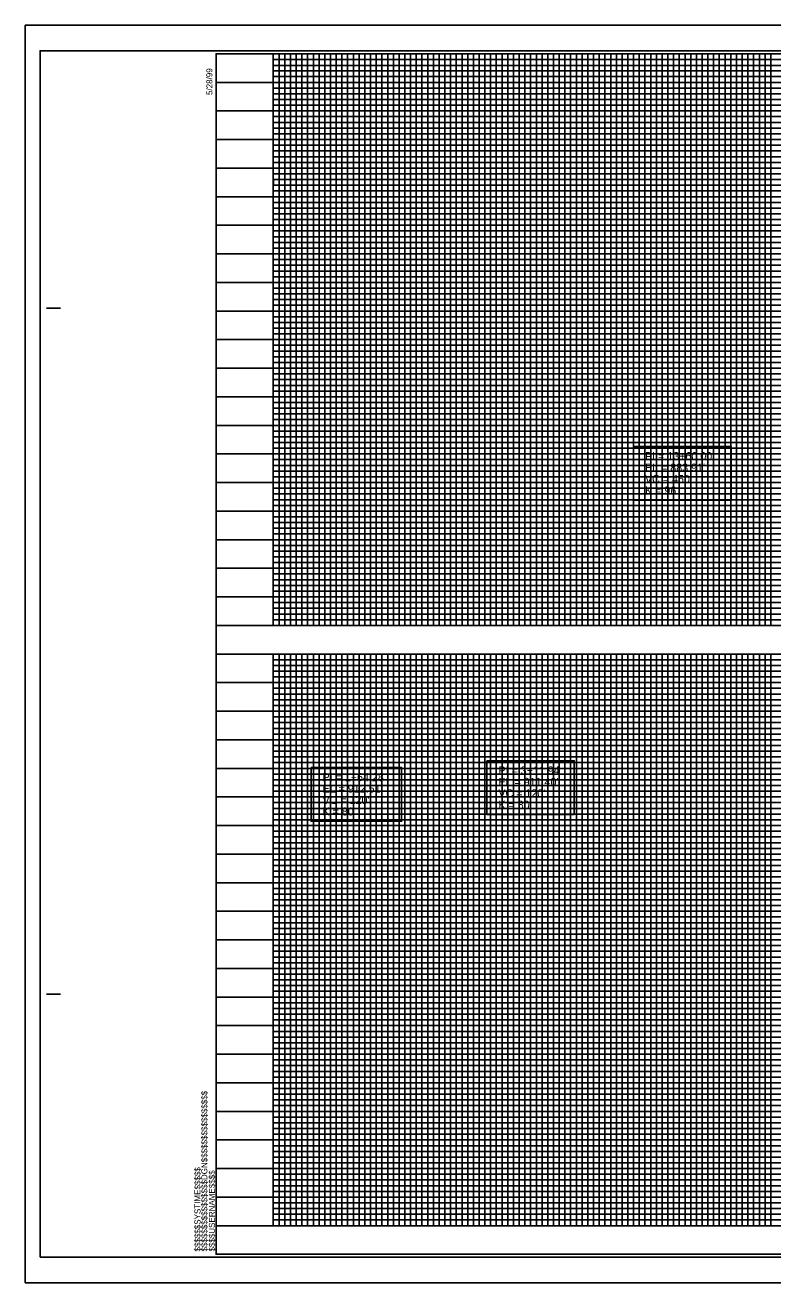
# Model space of a CAD drawing. Extents: x 1648862 to 1650889, y 802691 to 803791.
# Drawn here: x 1648862 to 1649516, y 802691 to 803791 of the extents above; entities that cross this region are included whole.
import ezdxf

# ---------------------------------------------------------------- set-up
doc = ezdxf.new("R2010")
doc.units = 0
for name, color, linetype in [('Prop Grid Mask', 7, 'Continuous'), ('Prop Vertical Profile Curve Label', 7, 'Continuous'), ('Prop VPI Label', 7, 'Continuous'), ('Sheet Cutting Line CELL', 7, 'Continuous'), ('Sheet DOT Grid CELL', 7, 'Continuous'), ('Sheet Layout Profile Border Port 1', 7, 'Continuous'), ('Sheet Layout Profile Border Port 2', 7, 'Continuous'), ('Sheet Plot Border Inside CELL', 7, 'Continuous'), ('Sheet Plot Border Outside CELL', 7, 'Continuous'), ('Sheet Profile CELL', 7, 'Continuous'), ('Sheet Profile Grid Major CELL', 7, 'Continuous'), ('Sheet Profile Grid Middle CELL', 7, 'Continuous'), ('Sheet Profile Grid Minor CELL', 7, 'Continuous')]:
    doc.layers.add(name, color=color, linetype=linetype)

msp = doc.modelspace()

# ---------------------------------------------------------------- linework, layer by layer
at = {"layer": 'Prop Grid Mask'}
for points in [[(1649394.3, 803422.6), (1649394.3, 803375.6), (1649479.6, 803375.6), (1649479.6, 803422.6)], [(1649266.1, 803147.7), (1649266.1, 803100.7), (1649342.4, 803100.7), (1649342.4, 803147.7)], [(1649112.3, 803141.8), (1649112.3, 803094.8), (1649191.4, 803094.8), (1649191.4, 803141.8)]]:
    msp.add_lwpolyline(points, close=True, dxfattribs=at)
at = {"layer": 'Sheet Cutting Line CELL'}
for p, q in [((1650546.3, 803791), (1648862.3, 803791)), ((1648862.3, 803791), (1648862.3, 802691)), ((1648862.3, 802691), (1650546.3, 802691))]:
    msp.add_line(p, q, dxfattribs=at)
at = {"layer": 'Sheet DOT Grid CELL'}
for p, q in [((1649079.3, 803266), (1649079.3, 803766)), ((1649129.3, 803266), (1649129.3, 803766)), ((1649179.3, 803266), (1649179.3, 803766)), ((1649229.3, 803266), (1649229.3, 803766)), ((1649279.3, 803266), (1649279.3, 803766)), ((1649329.3, 803266), (1649329.3, 803766)), ((1649379.3, 803266), (1649379.3, 803766)), ((1649429.3, 803266), (1649429.3, 803766)), ((1649479.3, 803266), (1649479.3, 803766)), ((1650329.2, 803716), (1649029.3, 803716)), ((1650329.2, 803666), (1649029.3, 803666)), ((1650329.3, 803616), (1649029.3, 803616)), ((1650529.3, 803566), (1649029.3, 803566)), ((1650529.3, 803516), (1649029.3, 803516)), ((1650529.3, 803466), (1649029.3, 803466)), ((1650529.3, 803416), (1649029.3, 803416)), ((1650529.3, 803366), (1649029.3, 803366)), ((1650529.3, 803316), (1649029.3, 803316)), ((1649029.3, 803241), (1650529.2, 803241)), ((1649079.3, 803241), (1649079.3, 802741)), ((1649129.3, 803241), (1649129.3, 802741)), ((1649179.3, 803241), (1649179.3, 802741)), ((1649229.3, 803241), (1649229.3, 802741)), ((1649279.3, 803241), (1649279.3, 802741)), ((1649329.3, 803241), (1649329.3, 802741)), ((1649379.3, 803241), (1649379.3, 802741)), ((1649429.3, 803241), (1649429.3, 802741)), ((1649479.3, 803241), (1649479.3, 802741)), ((1649029.3, 803191), (1650529.2, 803191)), ((1649029.3, 803141), (1650529.2, 803141)), ((1649029.3, 803091), (1650529.2, 803091)), ((1649029.3, 803041), (1650529.2, 803041)), ((1649029.3, 802991), (1650529.2, 802991)), ((1649029.3, 802941), (1650529.2, 802941)), ((1649029.3, 802891), (1650529.2, 802891)), ((1649029.3, 802841), (1650529.2, 802841)), ((1649029.3, 802791), (1650529.2, 802791))]:
    msp.add_line(p, q, dxfattribs=at)
at = {"layer": 'Sheet Layout Profile Border Port 1'}
msp.add_lwpolyline([(1649079.3, 803605), (1649079.3, 803266), (1650479.3, 803266), (1650479.3, 803605)], dxfattribs=at)
at = {"layer": 'Sheet Layout Profile Border Port 2'}
msp.add_lwpolyline([(1649079.3, 803241), (1650479.3, 803241), (1650479.3, 802741), (1649079.3, 802741)], close=True, dxfattribs=at)
at = {"layer": 'Sheet Plot Border Inside CELL'}
msp.add_lwpolyline([(1648875.3, 802713.5), (1650541.8, 802713.5), (1650541.8, 803768.6), (1648875.3, 803768.6)], close=True, dxfattribs=at)
at = {"layer": 'Sheet Plot Border Outside CELL'}
msp.add_lwpolyline([(1648862.3, 802691), (1650546.3, 802691), (1650546.3, 803791), (1648862.3, 803791)], close=True, dxfattribs=at)
at = {"layer": 'Sheet Profile CELL'}
for p, q in [((1648880.8, 803543.5), (1648893.3, 803543.5)), ((1649029.3, 803266), (1650529.3, 803266)), ((1649029.3, 803241), (1650529.3, 803241)), ((1648880.8, 802943.5), (1648893.3, 802943.5)), ((1650529.3, 802741), (1649029.3, 802741)), ((1649029.3, 802716), (1650529.3, 802716)), ((1649029.3, 802716), (1649029.3, 802716)), ((1649029.3, 802716), (1649029.3, 802716)), ((1649029.3, 802716), (1649029.3, 802716)), ((1649029.3, 802716), (1649029.3, 802716)), ((1649029.3, 802716), (1649029.3, 802716)), ((1649029.3, 802716), (1649029.3, 802716)), ((1649029.3, 802716), (1649029.3, 802716))]:
    msp.add_line(p, q, dxfattribs=at)
msp.add_lwpolyline([(1650529.3, 803766), (1649029.3, 803766), (1649029.3, 802716), (1650529.3, 802716)], close=True, dxfattribs=at)
msp.add_lwpolyline([(1649066.8, 802716), (1649066.8, 802716)], dxfattribs=at)
at = {"layer": 'Sheet Profile Grid Major CELL'}
msp.add_line((1649029.3, 802741), (1649029.3, 802741), dxfattribs=at)
for points in [[(1649079.3, 803766), (1649079.3, 803266), (1649129.3, 803266), (1649129.3, 803766), (1649179.3, 803766), (1649179.3, 803266), (1649229.3, 803266), (1649229.3, 803766), (1649279.3, 803766), (1649279.3, 803266), (1649329.3, 803266), (1649329.3, 803766), (1649379.3, 803766), (1649379.3, 803266), (1649429.3, 803266), (1649429.3, 803766), (1649479.3, 803766), (1649479.3, 803266), (1649529.3, 803266)], [(1649029.3, 803716), (1650329.3, 803716)], [(1650329.3, 803666), (1649029.3, 803666), (1649029.3, 803616), (1650329.3, 803616)], [(1650529.3, 803566), (1649029.3, 803566), (1649029.3, 803516), (1650529.3, 803516)], [(1650529.3, 803466), (1649029.3, 803466), (1649029.3, 803416), (1650529.3, 803416)], [(1650529.3, 803366), (1649029.3, 803366), (1649029.3, 803366), (1649029.3, 803316), (1650529.3, 803316)], [(1649079.3, 803241), (1649079.3, 802741), (1649129.3, 802741), (1649129.3, 803241), (1649179.3, 803241), (1649179.3, 802741), (1649229.3, 802741), (1649229.3, 803241), (1649279.3, 803241), (1649279.3, 802741), (1649329.3, 802741), (1649329.3, 803241), (1649379.3, 803241), (1649379.3, 802741), (1649429.3, 802741), (1649429.3, 803241), (1649479.3, 803241), (1649479.3, 802741), (1649529.3, 802741)], [(1650529.3, 803191), (1649029.3, 803191)], [(1650529.3, 803141), (1649029.3, 803141), (1649029.3, 803091), (1650529.3, 803091)], [(1650529.3, 803041), (1649029.3, 803041), (1649029.3, 802991), (1650529.3, 802991)], [(1650529.3, 802941), (1649029.3, 802941), (1649029.3, 802891), (1650529.3, 802891)], [(1650529.3, 802841), (1649029.3, 802841), (1649029.3, 802841), (1649029.3, 802791), (1650529.3, 802791)], [(1650529.3, 802741), (1649029.3, 802741)]]:
    msp.add_lwpolyline(points, dxfattribs=at)
at = {"layer": 'Sheet Profile Grid Middle CELL'}
msp.add_line((1649029.3, 803741), (1650179.3, 803741), dxfattribs=at)
for points in [[(1649104.3, 803766), (1649104.3, 803266), (1649154.3, 803266), (1649154.3, 803766), (1649204.3, 803766), (1649204.3, 803266), (1649254.3, 803266), (1649254.3, 803766), (1649304.3, 803766), (1649304.3, 803266), (1649354.3, 803266), (1649354.3, 803766), (1649404.3, 803766), (1649404.3, 803266), (1649454.3, 803266), (1649454.3, 803766), (1649504.3, 803766), (1649504.3, 803266), (1649554.3, 803266)], [(1650329.3, 803691), (1649029.3, 803691), (1649029.3, 803641), (1650329.3, 803641)], [(1650529.3, 803591), (1649029.3, 803591), (1649029.3, 803541), (1650354.3, 803541)], [(1650529.3, 803491), (1649029.3, 803491), (1649029.3, 803441), (1650529.3, 803441)], [(1650529.3, 803391), (1649029.3, 803391), (1649029.3, 803341), (1650529.3, 803341)], [(1650529.3, 803291), (1649029.3, 803291)], [(1649054.3, 803241), (1649104.3, 803241), (1649104.3, 802741), (1649154.3, 802741), (1649154.3, 803241), (1649204.3, 803241), (1649204.3, 802741), (1649254.3, 802741), (1649254.3, 803241), (1649304.3, 803241), (1649304.3, 802741), (1649354.3, 802741), (1649354.3, 803241), (1649404.3, 803241), (1649404.3, 802741), (1649454.3, 802741), (1649454.3, 803241), (1649504.3, 803241), (1649504.3, 802741), (1649554.3, 802741)], [(1649029.3, 803216), (1650529.3, 803216)], [(1650529.3, 803166), (1649029.3, 803166), (1649029.3, 803116), (1650529.3, 803116)], [(1650529.3, 803066), (1649029.3, 803066), (1649029.3, 803016), (1650529.3, 803016)], [(1650529.3, 802966), (1649029.3, 802966), (1649029.3, 802916), (1650529.3, 802916)], [(1650529.3, 802866), (1649029.3, 802866), (1649029.3, 802816), (1650529.3, 802816)], [(1650529.3, 802766), (1649029.3, 802766)]]:
    msp.add_lwpolyline(points, dxfattribs=at)
at = {"layer": 'Sheet Profile Grid Minor CELL'}
for p, q in [((1649079.3, 803761), (1650179.3, 803761)), ((1649079.3, 803756), (1649079.3, 803756)), ((1649079.3, 803756), (1649079.3, 803756)), ((1649079.3, 803756), (1649079.3, 803756)), ((1649079.3, 803756), (1649079.3, 803756)), ((1650179.3, 803756), (1649079.3, 803755.7)), ((1649079.3, 803751), (1650179.3, 803751)), ((1650329.2, 803631), (1649079.3, 803631)), ((1650329.3, 803626), (1649079.3, 803626)), ((1650329.3, 803621), (1649079.3, 803621)), ((1649079.3, 803611), (1650329.3, 803611)), ((1650329.3, 803606), (1649079.3, 803606)), ((1649079.3, 803601), (1650479.3, 803601)), ((1650479.3, 803581), (1649079.3, 803581)), ((1649079.3, 803576), (1650479.3, 803576)), ((1650479.3, 803556), (1649079.3, 803556)), ((1649079.3, 803551), (1650479.3, 803551)), ((1650479.3, 803531), (1649079.3, 803531)), ((1649079.3, 803526), (1650479.3, 803526)), ((1650479.3, 803521), (1649079.3, 803521)), ((1649079.3, 803511), (1650479.3, 803511)), ((1650479.3, 803506), (1649079.3, 803506)), ((1649079.3, 803501), (1650479.3, 803501)), ((1650479.3, 803496), (1649079.3, 803496)), ((1649079.3, 803486), (1650479.3, 803486)), ((1650479.3, 803481), (1649079.3, 803481)), ((1649079.3, 803476), (1650479.3, 803476)), ((1650479.3, 803471), (1649079.3, 803471)), ((1649079.3, 803461), (1650479.3, 803461)), ((1650479.3, 803456), (1649079.3, 803456)), ((1649079.3, 803451), (1650479.3, 803451)), ((1650479.3, 803446), (1649079.3, 803446)), ((1649079.3, 803436), (1650479.3, 803436)), ((1650479.3, 803431), (1649079.3, 803431)), ((1649079.3, 803426), (1650479.3, 803426)), ((1650479.3, 803421), (1649079.3, 803421)), ((1649079.3, 803411), (1650479.3, 803411)), ((1650479.3, 803406), (1649079.3, 803406)), ((1649079.3, 803401), (1650479.3, 803401)), ((1650479.3, 803396), (1649079.3, 803396)), ((1649079.3, 803386), (1650479.3, 803386)), ((1650479.3, 803381), (1649079.3, 803381)), ((1650479.3, 803376), (1649079.3, 803376)), ((1650479.3, 803371), (1649079.3, 803371)), ((1649079.3, 803361), (1650479.3, 803361)), ((1650479.3, 803356), (1649079.3, 803356)), ((1649079.3, 803351), (1650479.3, 803351)), ((1650479.3, 803346), (1649079.3, 803346)), ((1649079.3, 803336), (1650479.3, 803336)), ((1650479.3, 803331), (1649079.3, 803331)), ((1649079.3, 803326), (1650479.3, 803326)), ((1650479.3, 803321), (1649079.3, 803321)), ((1649079.3, 803311), (1650479.3, 803311)), ((1650479.3, 803306), (1649079.3, 803306)), ((1649079.3, 803301), (1650479.3, 803301)), ((1650479.3, 803296), (1649079.3, 803296)), ((1649079.3, 803286), (1650479.3, 803286)), ((1650479.3, 803281), (1649079.3, 803281)), ((1649079.3, 803276), (1650479.3, 803276)), ((1649079.3, 803236), (1650479.3, 803236)), ((1650479.3, 803231), (1649079.3, 803231)), ((1649079.3, 803226), (1650479.3, 803226)), ((1650479.3, 803221), (1649079.3, 803221)), ((1649079.3, 803211), (1650479.3, 803211)), ((1650479.3, 803206), (1649079.3, 803206)), ((1649079.3, 803201), (1650479.3, 803201)), ((1650479.3, 803196), (1649079.3, 803196)), ((1649079.3, 803186), (1650479.3, 803186)), ((1650479.3, 803181), (1649079.3, 803181)), ((1649079.3, 803176), (1650479.3, 803176)), ((1650479.3, 803171), (1649079.3, 803171)), ((1649079.3, 803161), (1650479.3, 803161)), ((1650479.3, 803156), (1649079.3, 803156)), ((1649079.3, 803151), (1650479.3, 803151)), ((1650479.3, 803146), (1649079.3, 803146)), ((1649079.3, 803136), (1650479.3, 803136)), ((1650479.3, 803131), (1649079.3, 803131)), ((1649079.3, 803126), (1650479.3, 803126)), ((1650479.3, 803121), (1649079.3, 803121)), ((1649079.3, 803111), (1650479.3, 803111)), ((1650479.3, 803106), (1649079.3, 803106)), ((1649079.3, 803101), (1650479.3, 803101)), ((1650479.3, 803096), (1649079.3, 803096)), ((1649079.3, 803086), (1650479.3, 803086)), ((1650479.3, 803081), (1649079.3, 803081)), ((1649079.3, 803076), (1650479.3, 803076)), ((1650479.3, 803071), (1649079.3, 803071)), ((1649079.3, 803061), (1650479.3, 803061)), ((1650479.3, 803056), (1649079.3, 803056)), ((1649079.3, 803051), (1650479.3, 803051)), ((1650479.3, 803046), (1649079.3, 803046.2)), ((1649079.3, 803036), (1650479.3, 803036)), ((1650479.3, 803031), (1649079.3, 803031)), ((1649079.3, 803026), (1650479.3, 803026)), ((1650479.3, 803021), (1649079.3, 803021)), ((1649079.3, 803011), (1650479.3, 803011)), ((1650479.3, 803006), (1649079.3, 803006)), ((1649079.3, 803001), (1650479.3, 803001)), ((1650479.3, 802996), (1649079.3, 802996)), ((1649079.3, 802986), (1650479.3, 802986)), ((1650479.3, 802981), (1649079.3, 802981)), ((1649079.3, 802976), (1650479.3, 802976)), ((1650479.3, 802971), (1649079.3, 802971)), ((1649079.3, 802961), (1650479.3, 802961)), ((1650479.3, 802956), (1649079.3, 802956)), ((1649079.3, 802951), (1650479.3, 802951)), ((1650479.3, 802946), (1649079.3, 802946)), ((1649079.3, 802936), (1650479.3, 802936)), ((1650479.3, 802931), (1649079.3, 802931)), ((1649079.3, 802926), (1650479.3, 802926)), ((1650479.3, 802921), (1649079.3, 802921)), ((1649079.3, 802911), (1650479.3, 802911)), ((1650479.3, 802906), (1649079.3, 802906)), ((1649079.3, 802901), (1650479.3, 802901)), ((1650479.3, 802896), (1649079.3, 802896)), ((1649079.3, 802886), (1650479.3, 802886)), ((1650479.3, 802881), (1649079.3, 802881)), ((1649079.3, 802876), (1650479.3, 802876)), ((1650479.3, 802871), (1649079.3, 802871)), ((1649079.3, 802861), (1650479.3, 802861)), ((1650479.3, 802856), (1649079.3, 802856)), ((1649079.3, 802851), (1650479.3, 802851)), ((1650479.3, 802846), (1649079.3, 802846)), ((1649079.3, 802836), (1650479.3, 802836)), ((1650479.3, 802831), (1649079.3, 802831)), ((1649079.3, 802826), (1650479.3, 802826)), ((1650479.3, 802821), (1649079.3, 802821)), ((1649079.3, 802811), (1650479.3, 802811)), ((1650479.3, 802806), (1649079.3, 802806)), ((1649079.3, 802801), (1650479.3, 802801)), ((1650479.3, 802796), (1649079.3, 802796)), ((1649079.3, 802786), (1650479.3, 802786)), ((1650479.3, 802781), (1649079.3, 802781)), ((1649079.3, 802776), (1650479.3, 802776)), ((1650479.3, 802771), (1649079.3, 802771)), ((1649079.3, 802761), (1650479.3, 802761)), ((1650479.3, 802756), (1649079.3, 802756)), ((1649079.3, 802751), (1650479.3, 802751)), ((1649079.3, 802746), (1650479.3, 802746))]:
    msp.add_line(p, q, dxfattribs=at)
for points in [[(1649084.3, 803766), (1649084.3, 803266), (1649089.3, 803266), (1649089.3, 803766), (1649094.3, 803766), (1649094.3, 803266), (1649099.3, 803266), (1649099.3, 803766), (1649109.3, 803766), (1649109.3, 803266), (1649114.3, 803266), (1649114.3, 803766), (1649119.3, 803766), (1649119.3, 803266), (1649124.3, 803266), (1649134.3, 803266), (1649139.3, 803266), (1649139.3, 803766), (1649144.3, 803766), (1649144.3, 803266), (1649149.3, 803266), (1649149.3, 803766), (1649159.3, 803766), (1649159.3, 803266), (1649164.3, 803266), (1649164.3, 803766), (1649169.3, 803766), (1649169.3, 803266), (1649174.3, 803266), (1649174.3, 803766), (1649184.3, 803766), (1649184.3, 803266), (1649189.3, 803266), (1649189.3, 803766), (1649194.3, 803766), (1649194.3, 803266), (1649199.3, 803266), (1649199.3, 803766), (1649209.3, 803766), (1649209.3, 803266), (1649214.3, 803266), (1649214.3, 803766), (1649219.3, 803766), (1649219.3, 803266), (1649224.3, 803266), (1649224.3, 803766), (1649234.3, 803766), (1649234.3, 803266), (1649239.3, 803266), (1649239.3, 803766), (1649244.3, 803766), (1649244.3, 803266), (1649249.3, 803266), (1649249.3, 803766), (1649259.3, 803766), (1649259.3, 803266), (1649264.3, 803266), (1649264.3, 803766), (1649269.3, 803766), (1649269.3, 803266), (1649274.3, 803266), (1649274.3, 803766), (1649284.3, 803766), (1649284.3, 803266), (1649289.3, 803266), (1649289.3, 803766), (1649294.3, 803766), (1649294.3, 803266)], [(1649124.3, 803266), (1649124.3, 803766), (1649134.3, 803766), (1649134.3, 803266)], [(1649294.3, 803266), (1649299.3, 803266), (1649299.3, 803766), (1649309.3, 803766), (1649309.3, 803266), (1649314.3, 803266), (1649314.3, 803766), (1649319.3, 803766), (1649319.3, 803266), (1649324.3, 803266), (1649324.3, 803766), (1649334.3, 803766), (1649334.3, 803266), (1649339.3, 803266), (1649339.3, 803766), (1649344.3, 803766), (1649344.3, 803266), (1649349.3, 803266), (1649349.3, 803766), (1649359.3, 803766), (1649359.3, 803266), (1649364.3, 803266), (1649364.3, 803766), (1649369.3, 803766), (1649369.3, 803266), (1649374.3, 803266), (1649374.3, 803766), (1649384.3, 803766), (1649384.3, 803266), (1649389.3, 803266), (1649389.3, 803766), (1649394.3, 803766), (1649394.3, 803266), (1649399.3, 803266), (1649399.3, 803766), (1649409.3, 803766), (1649409.3, 803266), (1649414.3, 803266), (1649414.3, 803766), (1649419.3, 803766), (1649419.3, 803266), (1649424.3, 803266), (1649424.3, 803766), (1649434.3, 803766), (1649434.3, 803266), (1649439.3, 803266), (1649439.3, 803766), (1649444.3, 803766), (1649444.3, 803266), (1649449.3, 803266), (1649449.3, 803766), (1649459.3, 803766), (1649459.3, 803266), (1649464.3, 803266), (1649464.3, 803766), (1649469.3, 803766), (1649469.3, 803266), (1649474.3, 803266), (1649474.3, 803766), (1649484.3, 803766), (1649484.3, 803266), (1649489.3, 803266), (1649489.3, 803766), (1649494.3, 803766), (1649494.3, 803266), (1649499.3, 803266), (1649499.3, 803766), (1649509.3, 803766), (1649509.3, 803266), (1649514.3, 803266), (1649514.3, 803766), (1649519.3, 803766)], [(1650179.3, 803746), (1649079.3, 803746), (1649079.3, 803736), (1650329.3, 803736)], [(1650329.2, 803731), (1649079.3, 803731), (1649079.3, 803726), (1650329.3, 803726)], [(1650329.3, 803721), (1649079.3, 803721), (1649079.3, 803711), (1650329.3, 803711)], [(1650329.3, 803706), (1649079.3, 803706), (1649079.3, 803701), (1650329.3, 803701)], [(1650329.3, 803696), (1649079.3, 803696), (1649079.3, 803686), (1650329.3, 803686)], [(1650329.3, 803681), (1649079.3, 803681), (1649079.3, 803676), (1650329.3, 803676)], [(1650329.3, 803671), (1649079.3, 803671), (1649079.3, 803661), (1650329.3, 803661)], [(1650329.3, 803655.9), (1649079.4, 803655.9), (1649079.4, 803651), (1650329.3, 803651)], [(1650329.3, 803646), (1649079.3, 803646), (1649079.3, 803636), (1650329.3, 803636)], [(1650479.3, 803596), (1649079.3, 803596), (1649079.3, 803586), (1650479.3, 803586)], [(1650479.3, 803571), (1649079.3, 803571), (1649079.3, 803561), (1650479.3, 803561)], [(1650479.3, 803546), (1649079.3, 803546), (1649079.3, 803536), (1650479.3, 803536)], [(1650479.3, 803271), (1649079.3, 803271)], [(1650479.3, 803271), (1649079.3, 803271)], [(1649079.3, 803241), (1649084.3, 803241), (1649084.3, 802741), (1649089.3, 802741), (1649089.3, 803241), (1649094.3, 803241), (1649094.3, 802741), (1649099.3, 802741), (1649099.3, 803241), (1649109.3, 803241), (1649109.3, 802741), (1649114.3, 802741), (1649114.3, 803241), (1649119.3, 803241), (1649119.3, 802741), (1649124.3, 802741), (1649134.3, 802741), (1649139.3, 802741), (1649139.3, 803241), (1649144.3, 803241), (1649144.3, 802741), (1649149.3, 802741), (1649149.3, 803241), (1649159.3, 803241), (1649159.3, 802741), (1649164.3, 802741), (1649164.3, 803241), (1649169.3, 803241), (1649169.3, 802741), (1649174.3, 802741), (1649174.3, 803241), (1649184.3, 803241), (1649184.3, 802741), (1649189.3, 802741), (1649189.3, 803241), (1649194.3, 803241), (1649194.3, 802741), (1649199.3, 802741), (1649199.3, 803241), (1649209.3, 803241), (1649209.3, 802741), (1649214.3, 802741), (1649214.3, 803241), (1649219.3, 803241), (1649219.3, 802741), (1649224.3, 802741), (1649224.3, 803241), (1649234.3, 803241), (1649234.3, 802741), (1649239.3, 802741), (1649239.3, 803241), (1649244.3, 803241), (1649244.3, 802741), (1649249.3, 802741), (1649249.3, 803241), (1649259.3, 803241), (1649259.3, 802741), (1649264.3, 802741), (1649264.3, 803241), (1649269.3, 803241), (1649269.3, 802741), (1649274.3, 802741), (1649274.3, 803241), (1649284.3, 803241), (1649284.3, 802741), (1649289.3, 802741), (1649289.3, 803241), (1649294.3, 803241), (1649294.3, 802741)], [(1649124.3, 802741), (1649124.3, 803241), (1649134.3, 803241), (1649134.3, 802741)], [(1649294.3, 802741), (1649299.3, 802741), (1649299.3, 803241), (1649309.3, 803241), (1649309.3, 802741), (1649314.3, 802741), (1649314.3, 803241), (1649319.3, 803241), (1649319.3, 802741), (1649324.3, 802741), (1649324.3, 803241), (1649334.3, 803241), (1649334.3, 802741), (1649339.3, 802741), (1649339.3, 803241), (1649344.3, 803241), (1649344.3, 802741), (1649349.3, 802741), (1649349.3, 803241), (1649359.3, 803241), (1649359.3, 802741), (1649364.3, 802741), (1649364.3, 803241), (1649369.3, 803241), (1649369.3, 802741), (1649374.3, 802741), (1649374.3, 803241), (1649384.3, 803241), (1649384.3, 802741), (1649389.3, 802741), (1649389.3, 803241), (1649394.3, 803241), (1649394.3, 802741), (1649399.3, 802741), (1649399.3, 803241), (1649409.3, 803241), (1649409.3, 802741), (1649414.3, 802741), (1649414.3, 803241), (1649419.3, 803241), (1649419.3, 802741), (1649424.3, 802741), (1649424.3, 803241), (1649434.3, 803241), (1649434.3, 802741), (1649439.3, 802741), (1649439.3, 803241), (1649444.3, 803241), (1649444.3, 802741), (1649449.3, 802741), (1649449.3, 803241), (1649459.3, 803241), (1649459.3, 802741), (1649464.3, 802741), (1649464.3, 803241), (1649469.3, 803241), (1649469.3, 802741), (1649474.3, 802741), (1649474.3, 803241), (1649484.3, 803241), (1649484.3, 802741), (1649489.3, 802741), (1649489.3, 803241), (1649494.3, 803241), (1649494.3, 802741), (1649499.3, 802741), (1649499.3, 803241), (1649509.3, 803241), (1649509.3, 802741), (1649514.3, 802741), (1649514.3, 803241), (1649519.3, 803241)]]:
    msp.add_lwpolyline(points, dxfattribs=at)

# ---------------------------------------------------------------- texts
at = {"layer": 'Prop Vertical Profile Curve Label'}
for s, p in [("VC = 450'", (1649404.3, 803390.6)), ('K = 96', (1649404.3, 803380.6)), ("VC = 120'", (1649276.1, 803115.7)), ("VC = 120'", (1649122.3, 803109.8)), ('K = 80', (1649276.1, 803105.7)), ('K = 80', (1649122.3, 803099.8))]:
    msp.add_text(s, height=7, dxfattribs=at).set_placement(p)
at = {"layer": 'Prop VPI Label'}
for s, p in [('PI = 13+60.00', (1649404.3, 803410.6)), ("EL = 883.91'", (1649404.3, 803400.6)), ('PI = 1+64.28', (1649122.3, 803129.8)), ('PI = 3+11.94', (1649276.1, 803135.7)), ("EL = 911.40'", (1649276.1, 803125.7)), ("EL = 912.51'", (1649122.3, 803119.8))]:
    msp.add_text(s, height=7, dxfattribs=at).set_placement(p)
at = {"layer": 'Sheet Profile CELL'}
for s, p in [('5/28/99', (1649026, 803729.9)), ('$$$$$$$$$$$$$$$$DGN$$$$$$$$$$$$$$$$', (1649021.6, 802718.4)), ('$$$$$$SYSTIME$$$$$', (1649015.6, 802718.4)), ('$$$$USERNAME$$$$', (1649028.2, 802718.4))]:
    msp.add_text(s, height=5.25, rotation=90, dxfattribs=at).set_placement(p)

doc.saveas('drawing.dxf')
